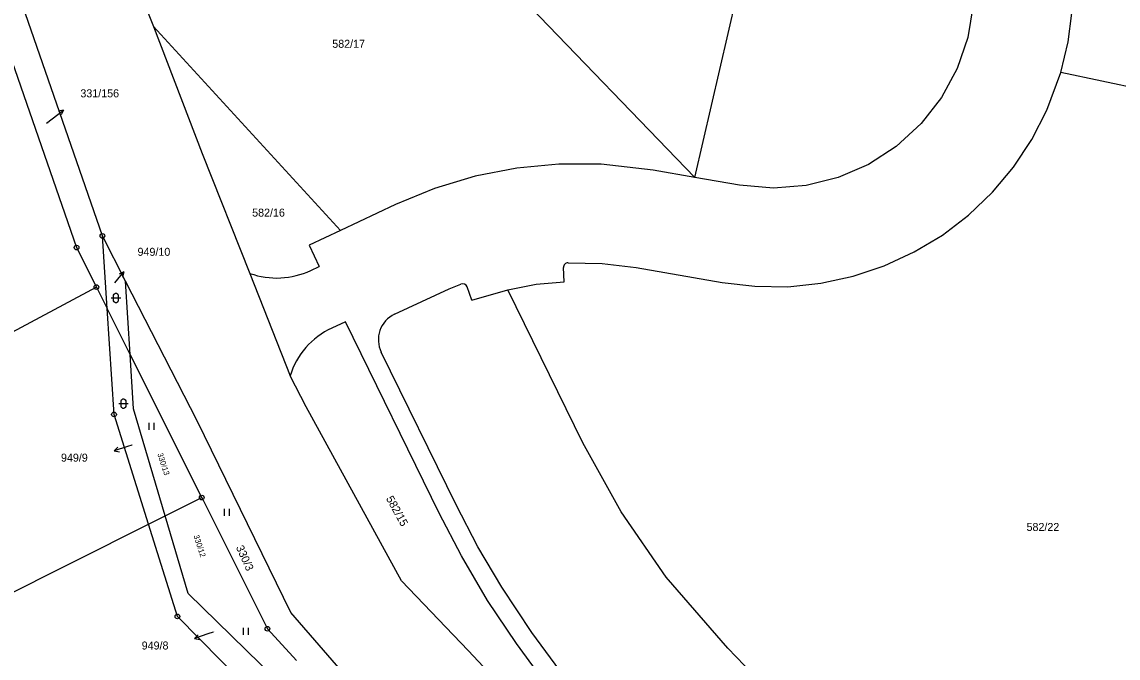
# Model space of a CAD drawing. Extents: x -770973 to -770265, y -1049936 to -1049427.
# Drawn here: x -770637.6 to -770521.2, y -1049596.8 to -1049529.2 of the extents above; entities that cross this region are included whole.
import ezdxf

# ---------------------------------------------------------------- set-up
doc = ezdxf.new("R2010")
doc.units = 0
for name, color, linetype in [('Vrstva 1', 7, 'Continuous'), ('Vrstva 13', 7, 'Continuous'), ('Vrstva 14', 7, 'Continuous'), ('Vrstva 16', 7, 'Continuous'), ('Vrstva 23', 7, 'Continuous'), ('Vrstva 28', 7, 'Continuous')]:
    doc.layers.add(name, color=color, linetype=linetype)

msp = doc.modelspace()

# ---------------------------------------------------------------- linework, layer by layer
at = {"layer": 'Vrstva 1'}
for p, q in [((-770566.13, -1049545.75), (-770555.82, -1049501.43)), ((-770629.53, -1049514.84), (-770623.61, -1049529.72)), ((-770588.17, -1049522.9), (-770566.13, -1049545.75)), ((-770629.03, -1049551.97), (-770638.35, -1049525.05)), ((-770536.55, -1049527.44), (-770537.13, -1049530.89)), ((-770526.48, -1049531.34), (-770526.08, -1049528.32)), ((-770639.88, -1049529.8), (-770631.77, -1049553.2)), ((-770623.61, -1049529.72), (-770618.44, -1049543.21)), ((-770603.76, -1049551.39), (-770623.61, -1049529.72)), ((-770537.13, -1049530.89), (-770538.27, -1049534.2)), ((-770527.26, -1049534.61), (-770526.48, -1049531.34)), ((-770538.27, -1049534.2), (-770539.93, -1049537.28)), ((-770528.74, -1049538.62), (-770527.26, -1049534.61)), ((-770488.51, -1049542.82), (-770527.26, -1049534.61)), ((-770539.93, -1049537.28), (-770542.08, -1049540.04)), ((-770530.34, -1049541.73), (-770528.74, -1049538.62)), ((-770542.08, -1049540.04), (-770544.75, -1049542.49)), ((-770532.27, -1049544.65), (-770530.34, -1049541.73)), ((-770618.44, -1049543.21), (-770613.36, -1049555.95)), ((-770544.75, -1049542.49), (-770547.69, -1049544.38)), ((-770580.55, -1049544.34), (-770585.03, -1049544.77)), ((-770576.05, -1049544.35), (-770580.55, -1049544.34)), ((-770570.54, -1049544.98), (-770576.05, -1049544.35)), ((-770547.69, -1049544.38), (-770550.9, -1049545.78)), ((-770589.44, -1049545.62), (-770593.75, -1049546.93)), ((-770585.03, -1049544.77), (-770589.44, -1049545.62)), ((-770566.13, -1049545.75), (-770570.54, -1049544.98)), ((-770534.52, -1049547.33), (-770532.27, -1049544.65)), ((-770561.39, -1049546.58), (-770566.13, -1049545.75)), ((-770557.78, -1049546.9), (-770561.39, -1049546.58)), ((-770554.3, -1049546.63), (-770557.78, -1049546.9)), ((-770550.9, -1049545.78), (-770554.3, -1049546.63)), ((-770593.75, -1049546.93), (-770597.91, -1049548.64)), ((-770537.04, -1049549.76), (-770534.52, -1049547.33)), ((-770597.91, -1049548.64), (-770603.76, -1049551.39)), ((-770539.82, -1049551.89), (-770537.04, -1049549.76)), ((-770603.76, -1049551.39), (-770607.07, -1049552.95)), ((-770628.53, -1049559.67), (-770629.03, -1049551.97)), ((-770626.57, -1049556.78), (-770629.03, -1049551.97)), ((-770542.83, -1049553.67), (-770539.82, -1049551.89)), ((-770631.77, -1049553.2), (-770629.67, -1049557.4)), ((-770607.07, -1049552.95), (-770606.01, -1049555.21)), ((-770546.01, -1049555.14), (-770542.83, -1049553.67)), ((-770579.57, -1049554.81), (-770575.95, -1049554.88)), ((-770575.95, -1049554.88), (-770572.35, -1049555.32)), ((-770613.36, -1049555.95), (-770609.1, -1049566.84)), ((-770606.9, -1049555.63), (-770606.01, -1049555.21)), ((-770579.98, -1049556.83), (-770580.05, -1049555.33)), ((-770572.35, -1049555.32), (-770563.2, -1049556.93)), ((-770549.32, -1049556.26), (-770546.01, -1049555.14)), ((-770618.97, -1049571.61), (-770626.57, -1049556.78)), ((-770626.09, -1049564.55), (-770626.57, -1049556.78)), ((-770592.21, -1049557.59), (-770590.95, -1049557.08)), ((-770585.96, -1049557.69), (-770582.98, -1049557.1)), ((-770582.98, -1049557.1), (-770579.98, -1049556.83)), ((-770563.2, -1049556.93), (-770559.73, -1049557.31)), ((-770559.73, -1049557.31), (-770556.23, -1049557.37)), ((-770556.23, -1049557.37), (-770552.75, -1049557)), ((-770552.75, -1049557), (-770549.32, -1049556.26)), ((-770629.67, -1049557.4), (-770652.75, -1049569.77)), ((-770629.67, -1049557.4), (-770628.53, -1049559.67)), ((-770598, -1049560.29), (-770592.21, -1049557.59)), ((-770589.79, -1049558.79), (-770590.3, -1049557.38)), ((-770589.79, -1049558.79), (-770585.96, -1049557.69)), ((-770578, -1049573.93), (-770585.96, -1049557.69)), ((-770627.8, -1049570.93), (-770628.53, -1049559.67)), ((-770626.09, -1049564.55), (-770628.53, -1049559.67)), ((-770603.23, -1049561.09), (-770604.66, -1049561.76)), ((-770593.26, -1049581.42), (-770603.23, -1049561.09)), ((-770591.46, -1049580.54), (-770599.42, -1049564.32)), ((-770625.73, -1049570.32), (-770626.09, -1049564.55)), ((-770618.48, -1049579.76), (-770626.09, -1049564.55)), ((-770607.4, -1049570.11), (-770609.1, -1049566.84)), ((-770597.28, -1049588.58), (-770607.4, -1049570.11)), ((-770624.14, -1049582.59), (-770627.8, -1049570.93)), ((-770622.35, -1049581.7), (-770625.73, -1049570.32)), ((-770609.02, -1049591.96), (-770618.97, -1049571.61)), ((-770573.93, -1049581.28), (-770578, -1049573.93)), ((-770622.35, -1049581.7), (-770618.48, -1049579.76)), ((-770618.48, -1049579.76), (-770611.51, -1049593.68)), ((-770589.15, -1049584.97), (-770591.46, -1049580.54)), ((-770624.14, -1049582.59), (-770622.35, -1049581.7)), ((-770619.91, -1049589.93), (-770622.35, -1049581.7)), ((-770590.91, -1049585.93), (-770593.26, -1049581.42)), ((-770569.16, -1049588.2), (-770573.93, -1049581.28)), ((-770647.61, -1049594.34), (-770624.14, -1049582.59)), ((-770621.07, -1049592.38), (-770624.14, -1049582.59)), ((-770586.62, -1049589.28), (-770589.15, -1049584.97)), ((-770588.12, -1049590.67), (-770590.91, -1049585.93)), ((-770590.2, -1049595.98), (-770597.28, -1049588.58)), ((-770562.62, -1049595.76), (-770569.16, -1049588.2)), ((-770610.71, -1049598.92), (-770619.91, -1049589.93)), ((-770583.43, -1049594.09), (-770586.62, -1049589.28)), ((-770585.07, -1049595.25), (-770588.12, -1049590.67)), ((-770599.06, -1049603.4), (-770609.02, -1049591.96)), ((-770612.88, -1049600.68), (-770621.07, -1049592.38)), ((-770611.51, -1049593.68), (-770608.42, -1049597.05)), ((-770580.45, -1049598.11), (-770583.43, -1049594.09)), ((-770582.65, -1049598.54), (-770585.07, -1049595.25)), ((-770527.14, -1049632.24), (-770562.62, -1049595.76)), ((-770585.18, -1049601.33), (-770590.2, -1049595.98))]:
    msp.add_line(p, q, dxfattribs=at)
for centre, radius, start, end in [((-770579.56, -1049555.31), 0.495, 91.713, 182.8682), ((-770610.52, -1049547.93), 8.51, 250.5043, 295.1674), ((-770590.78, -1049557.56), 0.514, 21.0394, 109.4103), ((-770596.74, -1049563), 2.99, 114.9142, 206.2652), ((-770601.18, -1049569.28), 8.29, 114.8216, 162.8704)]:
    msp.add_arc(centre, radius, start, end, dxfattribs=at)
at = {"layer": 'Vrstva 13'}
for p, q in [((-770634.97, -1049540), (-770634.35, -1049539.53)), ((-770625.9, -1049574.18), (-770626.36, -1049574.33)), ((-770617.28, -1049594.04), (-770617.83, -1049594.24))]:
    msp.add_line(p, q, dxfattribs=at)
at = {"layer": 'Vrstva 16'}
for p, q in [((-770634.35, -1049539.53), (-770633.16, -1049538.62)), ((-770633.16, -1049538.62), (-770633.71, -1049538.72)), ((-770633.16, -1049538.62), (-770633.4, -1049539.12)), ((-770627.71, -1049556.95), (-770626.75, -1049555.8)), ((-770626.75, -1049555.8), (-770627.26, -1049556.02)), ((-770626.75, -1049555.8), (-770626.88, -1049556.35)), ((-770626.36, -1049574.33), (-770627.78, -1049574.8)), ((-770627.78, -1049574.8), (-770627.39, -1049574.41)), ((-770627.78, -1049574.8), (-770627.23, -1049574.88)), ((-770617.83, -1049594.24), (-770619.25, -1049594.73)), ((-770619.25, -1049594.73), (-770618.86, -1049594.33)), ((-770619.25, -1049594.73), (-770618.69, -1049594.81))]:
    msp.add_line(p, q, dxfattribs=at)
at = {"layer": 'Vrstva 23'}
for p, q in [((-770627.84, -1049558.26), (-770627.79, -1049558.16)), ((-770627.84, -1049558.86), (-770627.84, -1049558.26)), ((-770627.79, -1049558.16), (-770627.74, -1049558.11)), ((-770627.74, -1049558.11), (-770627.64, -1049558.06)), ((-770627.64, -1049558.06), (-770627.54, -1049558.06)), ((-770627.54, -1049558.06), (-770627.44, -1049558.11)), ((-770627.44, -1049558.11), (-770627.39, -1049558.16)), ((-770627.39, -1049558.16), (-770627.34, -1049558.26)), ((-770627.34, -1049558.26), (-770627.34, -1049558.86)), ((-770628.09, -1049558.56), (-770627.09, -1049558.56)), ((-770627.79, -1049558.96), (-770627.84, -1049558.86)), ((-770627.74, -1049559.01), (-770627.79, -1049558.96)), ((-770627.64, -1049559.06), (-770627.74, -1049559.01)), ((-770627.54, -1049559.06), (-770627.64, -1049559.06)), ((-770627.44, -1049559.01), (-770627.54, -1049559.06)), ((-770627.39, -1049558.96), (-770627.44, -1049559.01)), ((-770627.34, -1049558.86), (-770627.39, -1049558.96)), ((-770627.3, -1049569.78), (-770626.3, -1049569.78)), ((-770627.05, -1049569.48), (-770627, -1049569.38)), ((-770627.05, -1049570.08), (-770627.05, -1049569.48)), ((-770627, -1049570.18), (-770627.05, -1049570.08)), ((-770627, -1049569.38), (-770626.95, -1049569.33)), ((-770626.95, -1049569.33), (-770626.85, -1049569.28)), ((-770626.85, -1049569.28), (-770626.75, -1049569.28)), ((-770626.75, -1049569.28), (-770626.65, -1049569.33)), ((-770626.65, -1049569.33), (-770626.6, -1049569.38)), ((-770626.6, -1049569.38), (-770626.55, -1049569.48)), ((-770626.55, -1049570.08), (-770626.6, -1049570.18)), ((-770626.55, -1049569.48), (-770626.55, -1049570.08)), ((-770626.95, -1049570.23), (-770627, -1049570.18)), ((-770626.85, -1049570.28), (-770626.95, -1049570.23)), ((-770626.75, -1049570.28), (-770626.85, -1049570.28)), ((-770626.65, -1049570.23), (-770626.75, -1049570.28)), ((-770626.6, -1049570.18), (-770626.65, -1049570.23)), ((-770624.08, -1049572.57), (-770624.08, -1049571.82)), ((-770623.58, -1049571.82), (-770623.58, -1049572.57)), ((-770616.07, -1049581.7), (-770616.07, -1049580.95)), ((-770615.57, -1049580.95), (-770615.57, -1049581.7)), ((-770614.04, -1049594.34), (-770614.04, -1049593.59)), ((-770613.54, -1049593.59), (-770613.54, -1049594.34))]:
    msp.add_line(p, q, dxfattribs=at)
at = {"layer": 'Vrstva 28'}
for centre, radius in [((-770629.03, -1049551.97), 0.25), ((-770629.03, -1049551.97), 0.005), ((-770631.77, -1049553.2), 0.25), ((-770631.77, -1049553.2), 0.005), ((-770629.67, -1049557.4), 0.25), ((-770629.67, -1049557.4), 0.005), ((-770627.8, -1049570.93), 0.25), ((-770627.8, -1049570.93), 0.005), ((-770618.48, -1049579.76), 0.25), ((-770618.48, -1049579.76), 0.005), ((-770621.07, -1049592.38), 0.25), ((-770621.07, -1049592.38), 0.005), ((-770611.51, -1049593.68), 0.25), ((-770611.51, -1049593.68), 0.005)]:
    msp.add_circle(centre, radius, dxfattribs=at)

# ---------------------------------------------------------------- texts
at = {"layer": 'Vrstva 14'}
for s, height, p in [('582/17', 0.85, (-770604.62, -1049531.99)), ('331/156', 0.05, (-770634.97, -1049540)), ('582/16', 0.85, (-770613.13, -1049549.92)), ('949/10', 0.05, (-770627.71, -1049556.95)), ('949/9', 0.05, (-770625.9, -1049574.18)), ('582/22', 0.85, (-770530.89, -1049583.3)), ('949/8', 0.05, (-770617.28, -1049594.04))]:
    msp.add_text(s, height=height, dxfattribs=at).set_placement(p)
for s, height, rotation, p in [('330/13', 0.6, 288, (-770623.2, -1049575.12)), ('582/15', 0.85, 298.8, (-770598.94, -1049579.86)), ('330/12', 0.6, 288, (-770619.36, -1049583.82)), ('330/3', 0.85, 294.3, (-770614.87, -1049585.04))]:
    msp.add_text(s, height=height, rotation=rotation, dxfattribs=at).set_placement(p)
at = {"layer": 'Vrstva 16'}
for s, p in [('331/156', (-770631.37, -1049537.25)), ('949/10', (-770625.3, -1049554.08)), ('949/9', (-770633.43, -1049575.94)), ('949/8', (-770624.86, -1049595.89))]:
    msp.add_text(s, height=0.85, dxfattribs=at).set_placement(p)

doc.saveas('drawing.dxf')
